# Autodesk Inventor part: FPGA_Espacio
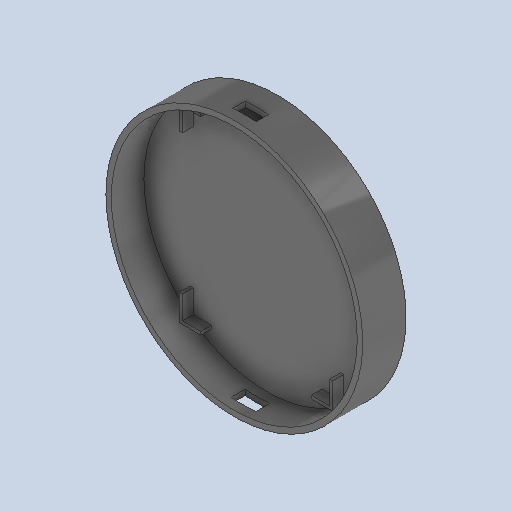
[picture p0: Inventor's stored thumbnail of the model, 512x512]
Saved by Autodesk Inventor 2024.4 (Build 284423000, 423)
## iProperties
Created: 2025-07
Part Number: FPGA_Espacio
Material: Generic
Document SubType Name: Modeling
Designer: AdminForWorker
Density: 1 g/cm^3
Appearance: Default
Title: FPGA_Espacio v4
Author: AdminForWorker
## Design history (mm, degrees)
feature "Body12"
feature "Body13"
feature "Body14"
feature "Body15"
feature "Body16"
body "Solid1"
body "Solid2"
body "Solid3"
body "Solid4"
body "Solid5"
